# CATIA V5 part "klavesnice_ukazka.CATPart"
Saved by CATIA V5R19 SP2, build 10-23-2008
Part number: Part1
Bounding box of the stored display mesh (mm): x -64 to 64, y -20 to 20.001, z 0 to 6.5
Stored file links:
  D:\Catia fórum\Modely - Otazky\klavesnice_ukazka.CATPart
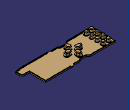
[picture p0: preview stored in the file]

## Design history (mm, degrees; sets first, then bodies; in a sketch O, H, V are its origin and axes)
Set1
  Plane1: type Offset, RefPlane xy-plane, Offset 1.5
  Point1: type OnPlane, Support Plane1, H -13.5, V 0, Direction (1, 0, 0)
  Line1: type PtDir, RefPoint Point1, Direction Plane1, Start 0, End 20
Body1 (main body)
Body2 "Klavesnice"
  Body3
    Sketch1 on face of Shell1, origin (0, 0, 1), H (1, 0, 0), V (0, 1, 0)
      line L1 (4, 23.8667) -> (10, 23.8667)
      line L2 (10, 23.8667) -> (10, -21.6865)
      line L3 (10, -21.6865) -> (4, -21.6865)
      line L4 (4, -21.6865) -> (4, 23.8667)
      line L5 (-65.428, 19.0013) -> (-61.6878, 19.0013)
      line L6 (-61.6878, 19.0013) -> (-61.6878, 9.0013)
      line L7 (-61.6878, 9.0013) -> (-65.428, 9.0013)
      line L8 (-65.428, 9.0013) -> (-65.428, 19.0013)
      reference intersected line E1 (-22.387, 19.0013) -> (-63, 19.0013) from face of Shell1
      distance L5 E1 = 0
      distance L5 L7 = 10
      distance L4 V = 4
      distance L4 L2 = 6
      horizontal: L1 H, L3 H, L5 H, L7 H
      vertical: L2 V, L4 V, L6 V, L8 V
    Sketch2 on xy-plane, origin (0, 0, 0), H (1, 0, 0), V (0, 1, 0)
      line L1 (-64, -20) -> (-64, -2.07)
      line L2 (-64, 20.0013) -> (-22, 20.0013)
      point P3 (-22, 20.0013)
      line L3 (-22, 20.0013) -> (-18.5, 16.815)
      line L4 (-18.5, 16.815) -> (-8.5, 16.815)
      point P5 (-8.5, 16.815)
      line L5 (-8.5, 16.815) -> (-6, 18.9775)
      point P6 (-6, 18.9775)
      line L6 (-6, 18.9775) -> (4, 18.9775)
      point P7 (4, 18.9775)
      line L7 (4, 18.9775) -> (6, 20.0013)
      point P8 (6, 20.0013)
      line L8 (6, 20.0013) -> (52, 20.0013)
      line L9 (52, 20.0013) -> (52, -7)
      line L10 (52, -7) -> (59, -7)
      line L11 (64, -12) -> (64, -17)
      line L12 (62, -19) -> (58.3266, -19)
      line L13 (57.3266, -20) -> (57.3266, -20)
      line L14 (57.3266, -20) -> (5.9974, -20)
      line L15 (5.9974, -20) -> (4, -18.9775)
      line L16 (4, -18.9775) -> (-6, -18.9775)
      line L17 (-6, -18.9775) -> (-8.5, -16.815)
      line L18 (-8.5, -16.815) -> (-18.5, -16.815)
      line L19 (-18.5, -16.815) -> (-21.9985, -20)
      point P17 (-21.9985, -20)
      line L20 (-21.9985, -20) -> (-64, -20)
      arc A1 centre (59, -12) radius 5 from (64, -12) to (59, -7) ccw
      arc A2 centre (62, -17) radius 2 from (64, -17) to (62, -19) cw
      arc A3 centre (58.3266, -20) radius 1 from (57.3266, -20) to (58.3266, -19) cw
      arc A4 centre (-64, -0.0437) radius 2.0263 from (-64, -2.07) to (-64, 1.9826) ccw
      point P27 (-64, -0.0437)
      line L21 (-64, 20.0013) -> (-64, 20.0013)
      point P29 (-64, 20.0013)
      line L22 (-64, 20.0013) -> (-64, 20.0013)
      line L23 (-64, 20.0013) -> (-64, 1.9826)
      distance H L8 = 20.0013
      distance H L14 = 20
      distance V L9 = 52
      distance H L6 = 18.9775
      distance H L4 = 16.815
      distance H L10 = 7
      distance L11 V = 64
      radius A1 = 5
      radius A2 = 2
      radius A3 = 1
      distance L12 L14 = 1
      distance P8 V = 6
      distance P7 V = 4
      distance V P6 = 6
      distance V P5 = 8.5
      length L4 = 10
      distance V P3 = 22
      distance V L1 = 64
      vertical: L1 V, L9 V, L11 V, L13 V, L23 V
      horizontal: L2 H, L4 H, L6 H, L8 H, L10 H, L12 H, L14 H, L16 H, L18 H
      coincidence: P8 L2, P17 L14, L20 L14, L1 L21, L1 L22, P29 L1, P27 L1
      tangency: A1 L11, A1 L10, A2 L11, A2 L12, A3 L13, A3 L12
      symmetry: L19 L3 H, L18 L4 H, L17 L5 H, L16 L6 H, L15 L7 H
    Pad1: profile Sketch2, direction (0, 0, 1), length 2
    Shell1: IntOffset 1, Face end face of Pad1, ExtOffset 0
    Thickness1: Thickness -0.5, Face face of Shell1
    Pocket1: profile Sketch1, direction (0, 0, 1), length 1
  Assemble1 "Podklad": tool Body3
  Body4
    Body5
      Sketch3 on Plane1, origin (0, 0, 1.5), H (1, 0, 0), V (0, 1, 0)
        circle A1 centre (-58, -13.75) radius 3
        point P1 (-58, -13.75)
        distance P1 V = 58
        distance P1 H = 13.75
        radius A1 = 3
      Pad2: profile Sketch3, direction (0, 0, 1), length 5, opposite side length 1
      Draft1: PullDir xy-plane, Angle -33, SupportToDraft face of Pad2 from Sketch3.A1, Neutral Plane1
      Fillet1: radius 0.9, on end face of Pad2
      RectPattern1: of the body so far, direction 1 instances 2, spacing 9, along xy-plane, direction 2 instances 4, spacing 9.2, along xy-plane
    Assemble2 "Horni kulata": tool Body5
    Body6
      Sketch4 on Plane1, origin (0, 0, 1.5), H (1, 0, 0), V (0, 1, 0)
        arc A1 centre (-13.5, -7.5) radius 3.5 from (-10.2002, -8.6667) to (-16.7998, -8.6667) ccw
        point P1 (-13.5, -7.5)
        arc A2 centre (-13.5, -12) radius 2 from (-15.3856, -12.6667) to (-11.6144, -12.6667) ccw
        point P2 (-13.5, -12)
        line L1 (-15.3856, -12.6667) -> (-16.7998, -8.6667)
        line L2 (-11.6144, -12.6667) -> (-10.2002, -8.6667)
        distance V P1 = 13.5
        distance H P1 = 7.5
        distance V P2 = 13.5
        distance P2 H = 12
        radius A2 = 2
        radius A1 = 3.5
        tangency: L1 A2, L1 A1, L2 A2, L2 A1
      Sketch5 on Plane1, origin (0, 0, 1.5), H (1, 0, 0), V (0, 1, 0)
        construction line L1 (-13.5, -7.5) -> (-13.5, -10.5)
        point P1 (-13.5, -7.5)
        line L2 (-10, -7.5) -> (-10, -10.5)
        line L3 (-17, -10.5) -> (-17, -7.5)
        arc A1 centre (-13.5, -10.5) radius 3.5 from (-10, -10.5) to (-17, -10.5) cw
        arc A2 centre (-13.5, -7.5) radius 3.5 from (-17, -7.5) to (-10, -7.5) cw
        distance L1 L2 = 3.5
        distance L1 V = 13.5
        length L1 = 3
        distance P1 H = 7.5
        vertical: L1 V
        tangency: A1 L2, A2 L2, A1 L3, A2 L3
      Pad3: profile Sketch5, direction (0, 0, -1), length 1
      Draft2: PullDir (0, 0, -1), Angle -33, SupportToDraft face of Pad3 from Sketch5.A1, Neutral start face of Pad3
      Pad4: profile Sketch4, direction (0, 0, 1), length 5
      Fillet2: radius 0.9, on edge [face of Pad4 from Sketch4.L2 | end face of Pad4]
      CircPattern1: of the body so far, instances 4, angular step 90, axis from Line1
    Assemble3 "Stredni asymetricka": tool Body6
  Assemble4 "Tlacitka": tool Body4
